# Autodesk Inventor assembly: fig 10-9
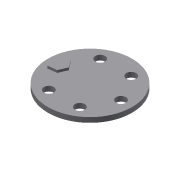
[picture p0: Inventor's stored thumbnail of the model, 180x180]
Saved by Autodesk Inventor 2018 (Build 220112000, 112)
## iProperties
Created: 2008-05
Part Number: fig 10-9
Document SubType Name: Assembly
Designer: CADCIM
Author: CADCIM
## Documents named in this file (3)
- E:\_Deepak\Inventor\Autodesk Inventor_2017_Project\Resources\Inventor_2018_Part\c10_Inv_2018\c10_inv_2018_prt\fig 10-9.iam
- E:\_Deepak\Inventor\Autodesk Inventor_2017_Project\Resources\Inventor_2018_Part\c10_Inv_2018\c10_inv_2018_prt\Part4.ipt
- E:\_Deepak\Inventor\Autodesk Inventor_2017_Project\Resources\Inventor_2018_Part\c10_Inv_2018\c10_inv_2018_prt\Part5.ipt
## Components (2 placed, 2 different names)
1. Part4:1
2. Part5:1
